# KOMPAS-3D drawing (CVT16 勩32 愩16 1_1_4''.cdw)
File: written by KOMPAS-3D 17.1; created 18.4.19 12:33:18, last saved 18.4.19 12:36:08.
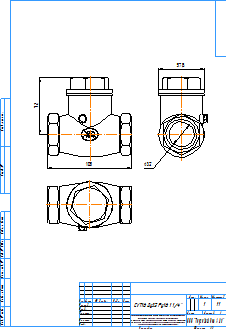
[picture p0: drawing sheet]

Sheet 1: A3, portrait

Title block, sheet 1: name: CVT16 Ду32 Ру16 1 1/4''; material: Внимание! Данный продукт является объектом авторского права ООО «Торговый Дом АДЛ». / Запрещается изменение, копирование, распространение / (в том числе путем копирования на другие сайты и ресурсы в Интернете) / или любое иное использование информации и объектов без предварительного / согласия правообладателя (ООО «Торговый Дом АДЛ»).; mass: 1; sheets: 1; organisation: ООО "Торговый дом АДЛ"; sheet format: A3; stored path: \\adlc.lan\data\АДЛ_ПКД\3D-модели\ADL production\Клапаны обратные ГРАНЛОК\CVT16\KOMPAS 2D\CVT16 Ду32 Ру16 1_1_4''.cdw

Views: Спереди 1, Проекционный вид 2, Проекционный вид 3
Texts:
  user
Dimensions and other numbers on the sheet: 105; 72; 57,8; 32; 1:1; 1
